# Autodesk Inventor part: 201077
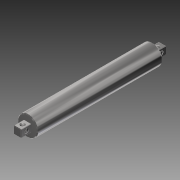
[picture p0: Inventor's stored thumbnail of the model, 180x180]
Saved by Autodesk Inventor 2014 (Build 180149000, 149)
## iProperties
Created: 2007-11
Part Number: 201077
Document SubType Name: Modeling
Designer: JJ
Density: 7.85 g/cm^3
Mass: 20.2939 g
Surface Area: 14.4088 cm^2
Volume: 2.58521 cm^3
Material: Steel
Description: MOTOR CONNECTING ROD
Appearance: Steel - Polished
Component Category: Lower Component
Author: JJ
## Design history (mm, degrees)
sketch "Sketch1"
  geometry: C1 r 4 at (0, 0); 1 further point
  constraints: 1 centre point, 1 coincident
  dimensions: "d0" = 8 diameter of C1
extrude "Extrusion1" new body sketch "Sketch1" stored distance "d1" = 50; taper "d2" = 0 deg
sketch "Sketch2"
  geometry: L1 (-5.6, 0)-(5.6, 0) reference; L2 (-1.5, -1.5)-(1.5, -1.5); L3 (1.5, -1.5)-(1.5, 1.5); L4 (1.5, 1.5)-(-1.5, 1.5); L5 (-1.5, 1.5)-(-1.5, -1.5); C1 r 4 at (0, 0) reference
  constraints: 8 end point, 2 parallel, 1 horizontal, 1 perpendicular
  dimensions: "d3" = 3 distance of L3.end L4.end (= d4); "d4" = 3 distance of L4.end L2.start; "d5" = 1.5 distance from line of C1.centre L4 (= 0.5 x d4); "d6" = 1.5 distance from line of L5 C1.centre (= 0.5 x d4)
extrude "Extrusion2" join sketch "Sketch2" distance "d7" = 4; taper "d8" = 0 deg
fillet "Fillet1" dims "d9" = 0.2
sketch "Sketch3"
  geometry: L1 (0, -4.8)-(0, 0); L2 (2.8, 0)-(2.8, -4.8); L3 (0, -2.4)-(2.8, -2.4); L4 (-4, -25)-(-4, 25) reference; L5 (-4, 25)-(4, 25) reference; L6 (4, 25)-(4, -25) reference; L7 (4, -25)-(1.5, -25) reference; L8 (1.5, -25)-(1.5, -28.8) reference; L9 (1.3, -29)-(-1.3, -29) reference; L10 (-1.5, -28.8)-(-1.5, -25) reference; L11 (-1.5, -25)-(-4, -25) reference; L12 (-1.5, -26.9)-(1.5, -26.9); L13 (1.5, -26.9)-(2.263, -26.9); L14 (-1.5, -26.9)-(-1.979, -26.9); L15 (-1.75, -26.9)-(1.75, -26.9); A1 r 1.75 centre (1.4, -2.4) between (-0.35, -2.4) and (3.15, -2.4); A2 r 0.2 centre (1.3, -28.8) between (1.3, -29) and (1.5, -28.8) reference; A3 r 0.2 centre (-1.3, -28.8) between (-1.5, -28.8) and (-1.3, -29) reference; A4 r 1.75 centre (0, -26.9) between (-1.75, -26.9) and (1.75, -26.9); 1 further point
  constraints: 14 end point, 6 midpoint, 4 point on circle, 4 point on line, 3 collinear, 2 centre point, 1 coincident
  dimensions: "d10" = 1.75 radius of A1; "d11" = 3.5 diameter of A4
revolve "Revolution1" sketch "Sketch3" stored, may be unused: angle "d12" = 90 deg
mirror "Mirror1"
chamfer "Chamfer2" distance "d16" = 0.3; stored, may be unused: second distance "d17" = 2, angle "d18" = 45 deg
workplane "Work Plane1"
split "Split1"
split "Split2"
body "Solid1"
node "Project Cut Edges1"
other parameters: "d19" = -50.5
